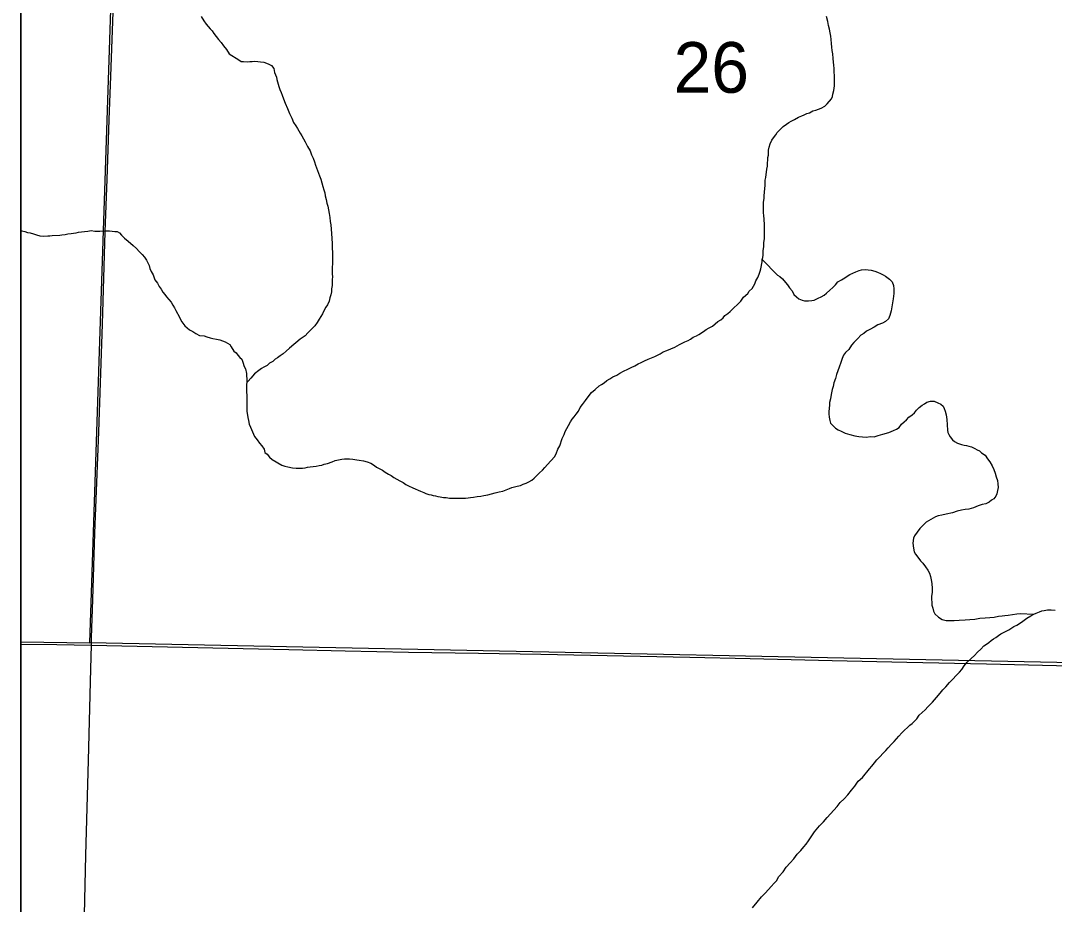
# Model space of a CAD drawing. Extents: x 2.4 to 73.1, y 4.5 to 25.6.
# Drawn here: x 29.4974 to 29.9242, y 22.0706 to 22.4355 of the extents above; entities that cross this region are included whole.
import ezdxf

# ---------------------------------------------------------------- set-up
doc = ezdxf.new("R2010")
doc.units = 0
for name, color, linetype in [('GM_X_County_Road', 7, 'Continuous'), ('GM_X_Interchange_Ramps', 7, 'Continuous'), ('GM_X_Minor_River', 7, 'Continuous'), ('GM_X_Section', 7, 'Continuous'), ('GM_X_Section_Text', 7, 'Continuous'), ('GM_X_Township_Road', 7, 'Continuous'), ('GM_X_US_Shield', 7, 'Continuous'), ('SH_Cut_Line', 7, 'Continuous'), ('SH_Data', 7, 'Continuous')]:
    doc.layers.add(name, color=color, linetype=linetype)

msp = doc.modelspace()

# ---------------------------------------------------------------- linework, layer by layer
at = {"layer": 'GM_X_County_Road'}
for points in [[(29.49738, 22.17807), (29.51234, 22.17781), (29.52657, 22.17755)], [(29.52657, 22.17755), (29.60806, 22.17578), (29.63137, 22.17527), (29.65748, 22.17474), (29.68638, 22.17428), (29.71218, 22.17383), (29.77371, 22.17258), (29.79858, 22.17203), (29.83246, 22.17129), (29.86322, 22.17062), (29.89616, 22.16995), (29.92506, 22.16924), (29.98504, 22.16792), (30.01954, 22.16724), (30.02726, 22.16709)]]:
    msp.add_lwpolyline(points, dxfattribs=at)
at = {"layer": 'GM_X_Interchange_Ramps'}
msp.add_lwpolyline([(29.49738, 24.68879), (29.49738, 21.67933)], dxfattribs=at)
at = {"layer": 'GM_X_Minor_River'}
for points in [[(29.57195, 22.43721), (29.57306, 22.43548), (29.57399, 22.43413), (29.57474, 22.43317), (29.57567, 22.43221), (29.57642, 22.43125), (29.57717, 22.43028), (29.5781, 22.42894), (29.57903, 22.42779), (29.58015, 22.42644), (29.58108, 22.42509), (29.58238, 22.42355), (29.5835, 22.42182), (29.58745, 22.41929), (29.58839, 22.41871), (29.58935, 22.41869), (29.59086, 22.41848), (29.59201, 22.41865), (29.59296, 22.41863), (29.59391, 22.41881), (29.59524, 22.4186), (29.59638, 22.41858), (29.59771, 22.41837), (29.59884, 22.41797), (29.59979, 22.41757), (29.60092, 22.41699), (29.60185, 22.41583)], [(29.79336, 22.31836), (29.79472, 22.31967), (29.79588, 22.32136), (29.79762, 22.32286), (29.7982, 22.3238), (29.79936, 22.32492), (29.79995, 22.32586), (29.80053, 22.3268), (29.80093, 22.32812), (29.80172, 22.32944), (29.80231, 22.33076), (29.80271, 22.33209), (29.80291, 22.33303), (29.80353, 22.33587), (29.80354, 22.33682), (29.80375, 22.33777), (29.80395, 22.33872), (29.80397, 22.33967), (29.80398, 22.34062), (29.8042, 22.34213), (29.80422, 22.34384), (29.80444, 22.34536), (29.80445, 22.34631), (29.80448, 22.34783), (29.80449, 22.34897), (29.80451, 22.35011), (29.80453, 22.35125), (29.80438, 22.35353), (29.80421, 22.35505), (29.80404, 22.3562), (29.80406, 22.35753), (29.80407, 22.35848), (29.80409, 22.35961), (29.8041, 22.36056), (29.80432, 22.36208), (29.80434, 22.36322), (29.80457, 22.36626), (29.80478, 22.36739), (29.8048, 22.36872), (29.80482, 22.36967), (29.80503, 22.37081), (29.80523, 22.37195), (29.80525, 22.3729), (29.80546, 22.37422), (29.80567, 22.37536), (29.80569, 22.37669), (29.8059, 22.37802), (29.80591, 22.37897), (29.80612, 22.37991), (29.80614, 22.38105), (29.80615, 22.382), (29.80636, 22.38333), (29.80676, 22.38465), (29.80755, 22.38616), (29.80814, 22.3871), (29.80911, 22.38842), (29.80969, 22.38936), (29.81066, 22.39029), (29.8122, 22.39179), (29.81355, 22.39272), (29.81451, 22.39346), (29.81547, 22.39402), (29.81681, 22.39475), (29.81854, 22.39568), (29.81988, 22.39623), (29.82083, 22.39659), (29.82198, 22.39714), (29.82313, 22.3975), (29.82448, 22.39824), (29.82562, 22.3986), (29.82677, 22.39897), (29.82791, 22.39933), (29.82945, 22.40025), (29.83042, 22.40119), (29.83216, 22.40325), (29.83256, 22.4042), (29.83276, 22.40514), (29.83316, 22.40666), (29.83339, 22.40855), (29.83341, 22.41007), (29.83343, 22.41159), (29.83345, 22.41292), (29.83328, 22.41425), (29.83331, 22.41577), (29.83314, 22.41711), (29.83297, 22.41844), (29.8328, 22.41996), (29.83264, 22.42186), (29.83247, 22.4232), (29.8323, 22.42453), (29.83214, 22.42605), (29.83197, 22.42776), (29.83181, 22.4291), (29.83164, 22.43043), (29.83128, 22.43196), (29.83092, 22.43348), (29.83057, 22.4352), (29.83003, 22.4373)], [(29.60185, 22.41583), (29.60221, 22.41412), (29.60257, 22.41316), (29.60294, 22.4122), (29.60311, 22.41125), (29.60348, 22.4103), (29.60365, 22.40934), (29.60402, 22.40839), (29.60438, 22.40705), (29.60493, 22.4059), (29.60529, 22.40476), (29.60584, 22.40323), (29.60657, 22.40151), (29.60749, 22.39921), (29.60841, 22.39711), (29.60933, 22.39519), (29.61006, 22.39347), (29.61099, 22.39213), (29.61173, 22.39097), (29.61229, 22.39002), (29.61284, 22.38906), (29.6134, 22.38791), (29.61414, 22.38676), (29.61488, 22.38541), (29.6158, 22.3835), (29.61691, 22.38177), (29.61746, 22.38005), (29.6182, 22.37871), (29.61875, 22.37718), (29.6191, 22.37585), (29.62038, 22.3726), (29.62075, 22.37145), (29.6213, 22.37011), (29.62165, 22.36859), (29.6222, 22.36706), (29.62256, 22.36572), (29.62292, 22.36439), (29.62309, 22.36324), (29.62345, 22.36172), (29.6238, 22.36019), (29.62416, 22.35886), (29.62452, 22.35733), (29.62469, 22.35581), (29.62504, 22.35428), (29.62521, 22.35257), (29.62537, 22.35124), (29.62553, 22.34934), (29.6257, 22.34762), (29.62586, 22.34553), (29.62601, 22.34344), (29.62598, 22.34154), (29.62615, 22.33982), (29.62612, 22.33812), (29.6261, 22.3366), (29.62607, 22.33507), (29.62605, 22.33375), (29.62603, 22.33223), (29.62601, 22.3309), (29.62618, 22.32975), (29.62597, 22.32862), (29.62595, 22.32729), (29.62593, 22.32615), (29.62572, 22.32482), (29.6257, 22.32349), (29.62549, 22.32235), (29.62509, 22.32103), (29.62469, 22.31971), (29.6241, 22.3182), (29.62332, 22.31726), (29.62273, 22.31594), (29.62194, 22.31443), (29.62136, 22.3133), (29.62058, 22.31217), (29.6198, 22.31085), (29.61883, 22.30954), (29.61767, 22.30842), (29.6167, 22.30748), (29.61593, 22.30655), (29.61477, 22.30542), (29.61284, 22.30393), (29.60841, 22.3002), (29.60706, 22.29909), (29.60571, 22.29797), (29.60456, 22.29704), (29.6034, 22.29629), (29.60244, 22.29574), (29.60148, 22.2948), (29.60014, 22.29407), (29.59917, 22.29313), (29.59783, 22.29239), (29.59687, 22.29184), (29.59571, 22.2911), (29.59398, 22.2896), (29.59243, 22.28792), (29.59127, 22.28661), (29.59088, 22.28623), (29.59089, 22.28642)], [(29.49738, 22.34879), (29.49791, 22.3487), (29.49905, 22.34849), (29.50018, 22.34809), (29.50132, 22.34788), (29.50265, 22.34748), (29.50397, 22.34708), (29.5053, 22.34668), (29.50681, 22.34647), (29.50853, 22.34663), (29.50948, 22.34661), (29.51043, 22.34679), (29.51348, 22.34693), (29.51443, 22.3471), (29.51577, 22.34727), (29.51691, 22.34745), (29.51824, 22.34761), (29.5192, 22.34779), (29.52034, 22.34796), (29.52129, 22.34814), (29.52244, 22.34831), (29.52377, 22.34848), (29.52511, 22.34865), (29.52644, 22.34881), (29.52796, 22.3486), (29.53005, 22.34857), (29.53196, 22.34873), (29.53405, 22.34869), (29.53632, 22.34847), (29.53728, 22.34845), (29.53822, 22.34787), (29.53896, 22.34691), (29.54028, 22.34575), (29.54178, 22.34439), (29.54384, 22.34265), (29.54515, 22.34149), (29.54627, 22.34014), (29.54759, 22.33898), (29.54852, 22.33782), (29.54926, 22.33667), (29.54982, 22.33552), (29.55037, 22.33438), (29.55073, 22.33323), (29.55128, 22.33189), (29.55202, 22.33055), (29.55275, 22.32845), (29.55387, 22.3271), (29.55461, 22.32576), (29.55535, 22.32461), (29.55609, 22.32345), (29.55684, 22.32249), (29.55758, 22.32153), (29.55852, 22.32038), (29.55945, 22.31922), (29.56019, 22.31807), (29.56093, 22.31692), (29.56149, 22.31577), (29.56297, 22.31308), (29.56333, 22.31213), (29.56389, 22.31117), (29.56519, 22.30944), (29.56613, 22.30866), (29.56707, 22.30789), (29.56839, 22.30711), (29.56971, 22.30633)], [(29.80354, 22.33682), (29.80991, 22.33045), (29.81085, 22.32987), (29.81198, 22.3289), (29.81309, 22.32736), (29.81403, 22.3264), (29.81477, 22.32524), (29.81589, 22.3239), (29.81663, 22.32236), (29.81776, 22.3214), (29.81869, 22.32062), (29.82002, 22.32003), (29.82096, 22.31983), (29.82268, 22.3198), (29.82401, 22.31997), (29.82496, 22.32014), (29.82669, 22.32088), (29.82784, 22.32143), (29.82918, 22.32217), (29.83014, 22.32291), (29.83149, 22.32422), (29.83265, 22.32534), (29.83381, 22.32646), (29.83478, 22.32759), (29.83631, 22.32851), (29.83766, 22.32925), (29.83862, 22.33), (29.83977, 22.33074), (29.84092, 22.33129), (29.84226, 22.33184), (29.8436, 22.33239), (29.84456, 22.33256), (29.84608, 22.33273), (29.84855, 22.3325), (29.85006, 22.33209), (29.8512, 22.3317), (29.85233, 22.33111), (29.85346, 22.33052), (29.85441, 22.32994), (29.8561, 22.32877), (29.85722, 22.32761), (29.85777, 22.32608), (29.85794, 22.32475), (29.85791, 22.32285), (29.85768, 22.32057), (29.85726, 22.31811), (29.85684, 22.31565), (29.85624, 22.31376), (29.85565, 22.31244), (29.85449, 22.31131), (29.85315, 22.31057), (29.85124, 22.30985), (29.8497, 22.30892), (29.84798, 22.308), (29.84663, 22.30726), (29.84548, 22.30633), (29.84432, 22.30559), (29.84297, 22.30428), (29.84142, 22.30259), (29.84046, 22.30147), (29.83929, 22.29977), (29.83794, 22.29847), (29.83716, 22.29734), (29.83657, 22.29602), (29.83597, 22.29432), (29.83537, 22.29243), (29.83477, 22.29092), (29.83418, 22.28941), (29.83377, 22.2877), (29.83318, 22.286), (29.83277, 22.28449), (29.83237, 22.28316), (29.83196, 22.28108), (29.83174, 22.27937), (29.83134, 22.27786), (29.83132, 22.27672), (29.83109, 22.27406), (29.83107, 22.27311), (29.83124, 22.27178), (29.83141, 22.27045), (29.83177, 22.2693), (29.83383, 22.26718), (29.83496, 22.26659), (29.8361, 22.266), (29.8378, 22.26522), (29.83969, 22.26462), (29.84177, 22.26401), (29.84348, 22.2638), (29.845, 22.26358), (29.84652, 22.26356), (29.84823, 22.26372), (29.84975, 22.2637), (29.85147, 22.26424), (29.85338, 22.26478), (29.85587, 22.2655), (29.85778, 22.26623), (29.85893, 22.26678), (29.86008, 22.26752), (29.86105, 22.26884), (29.86221, 22.26977), (29.86318, 22.2707)], [(29.66964, 22.239), (29.67059, 22.2388), (29.67192, 22.23859), (29.67306, 22.23857), (29.67439, 22.23836), (29.67572, 22.23834), (29.67705, 22.23831), (29.67838, 22.23829), (29.67971, 22.23827), (29.68104, 22.23825), (29.68218, 22.23842), (29.68314, 22.2386), (29.68428, 22.23877), (29.68581, 22.23894), (29.68733, 22.2391), (29.68867, 22.23946), (29.69019, 22.23963), (29.69172, 22.24017), (29.69325, 22.24053), (29.69496, 22.24088), (29.69649, 22.24124), (29.69783, 22.24179), (29.69917, 22.24233), (29.70013, 22.2427), (29.70128, 22.24306), (29.70242, 22.24323), (29.70376, 22.24359), (29.70491, 22.24414), (29.70605, 22.2445), (29.7072, 22.24506), (29.70836, 22.2458), (29.70932, 22.24654), (29.71067, 22.24785), (29.71164, 22.24879), (29.71279, 22.24991), (29.71376, 22.25103), (29.71492, 22.25215), (29.71782, 22.25534), (29.71842, 22.25666), (29.71921, 22.25855), (29.71999, 22.25986), (29.72099, 22.26289), (29.72177, 22.26459), (29.72217, 22.26591), (29.72354, 22.26836), (29.72433, 22.26987), (29.72511, 22.27099), (29.72588, 22.27193), (29.72666, 22.27306), (29.72763, 22.27418), (29.72841, 22.27569), (29.72938, 22.27701), (29.73055, 22.2787), (29.73172, 22.2802), (29.73307, 22.28189), (29.73462, 22.28319), (29.73616, 22.28469), (29.73712, 22.28524), (29.73827, 22.28599), (29.73943, 22.28692), (29.74058, 22.28766), (29.74192, 22.2884), (29.74346, 22.28913), (29.7448, 22.28987), (29.74634, 22.2908), (29.74806, 22.29153), (29.7494, 22.29227), (29.75094, 22.29301), (29.75228, 22.29374), (29.75362, 22.29429), (29.75496, 22.29503), (29.75649, 22.29577), (29.75783, 22.29632), (29.75917, 22.29686), (29.76032, 22.29742), (29.76147, 22.29797), (29.76263, 22.29871), (29.76416, 22.29926), (29.76741, 22.30072), (29.76837, 22.30128), (29.76933, 22.30183), (29.77048, 22.30239), (29.77163, 22.30294), (29.77297, 22.30349), (29.77393, 22.30404), (29.77508, 22.30478), (29.77642, 22.30533), (29.77738, 22.30589), (29.7793, 22.30719), (29.78046, 22.30793), (29.78161, 22.30867), (29.78295, 22.30941), (29.78411, 22.31034), (29.78527, 22.31127), (29.78642, 22.31201), (29.78738, 22.31276), (29.78816, 22.3137), (29.78931, 22.31463), (29.79027, 22.31537), (29.79182, 22.31687), (29.79336, 22.31836)], [(29.56971, 22.30633), (29.57122, 22.30554), (29.57312, 22.30532), (29.57425, 22.30493), (29.57558, 22.30452), (29.57671, 22.30432), (29.57823, 22.30391), (29.57956, 22.3037), (29.58069, 22.3033), (29.58183, 22.30291), (29.58277, 22.30232), (29.58371, 22.30174), (29.58426, 22.30078), (29.58538, 22.29905), (29.58632, 22.29827), (29.58706, 22.29731), (29.58781, 22.29635), (29.58875, 22.29577), (29.58911, 22.29443), (29.58965, 22.29271), (29.59021, 22.29175), (29.59056, 22.28985), (29.59055, 22.2889), (29.59071, 22.28756), (29.59069, 22.28624), (29.59068, 22.28529), (29.59066, 22.28415), (29.59064, 22.283), (29.59063, 22.28206), (29.5908, 22.28091), (29.59078, 22.27958), (29.59075, 22.27787), (29.59074, 22.27692), (29.59072, 22.27578), (29.59069, 22.27407), (29.59105, 22.27255), (29.59123, 22.2716), (29.5914, 22.27045), (29.59175, 22.26893), (29.5923, 22.26759), (29.59303, 22.26568), (29.59396, 22.26376), (29.59508, 22.26241), (29.596, 22.26107), (29.59694, 22.25991), (29.59787, 22.25857), (29.59823, 22.25723), (29.59917, 22.25646), (29.6001, 22.2553), (29.60123, 22.25434), (29.60518, 22.25199), (29.60651, 22.25159), (29.60764, 22.2512), (29.60954, 22.25078), (29.61106, 22.25076), (29.61239, 22.25074), (29.61372, 22.25072), (29.61486, 22.25089), (29.61582, 22.25107), (29.61696, 22.25124), (29.61811, 22.25141), (29.61944, 22.25158), (29.62058, 22.25175), (29.62173, 22.25192), (29.62268, 22.25229), (29.62402, 22.25265), (29.62593, 22.25338), (29.62727, 22.25392), (29.62861, 22.25409), (29.62994, 22.25445), (29.63109, 22.25462), (29.63223, 22.25461), (29.63318, 22.25459), (29.63451, 22.25438), (29.63622, 22.25416), (29.63716, 22.25396), (29.63887, 22.25374), (29.64039, 22.25334), (29.6419, 22.25274), (29.64341, 22.25177), (29.64435, 22.25118), (29.64567, 22.2504), (29.6468, 22.24981), (29.64793, 22.24904), (29.64925, 22.24825), (29.65038, 22.24767), (29.65151, 22.24689), (29.65264, 22.24611), (29.65396, 22.24552), (29.65528, 22.24474), (29.65641, 22.24396), (29.65754, 22.24337), (29.65924, 22.24259), (29.66245, 22.24121), (29.66377, 22.24061), (29.66472, 22.24022), (29.66585, 22.23982), (29.6668, 22.23962), (29.66775, 22.23941), (29.66869, 22.23921), (29.66964, 22.239)], [(29.86318, 22.2707), (29.86414, 22.27183), (29.86549, 22.27276), (29.86645, 22.2735), (29.86723, 22.27463), (29.86839, 22.27575), (29.86955, 22.27668), (29.8705, 22.27724), (29.87147, 22.27798), (29.873, 22.27834), (29.87452, 22.27832), (29.87603, 22.27772), (29.87735, 22.27713), (29.87829, 22.27636), (29.87866, 22.2754), (29.87902, 22.27425), (29.87956, 22.27273), (29.87972, 22.27082), (29.88004, 22.26645), (29.88021, 22.26549), (29.88058, 22.26454), (29.88113, 22.26358), (29.88207, 22.26243), (29.883, 22.26165), (29.88414, 22.26106), (29.88584, 22.26047), (29.88698, 22.26026), (29.88792, 22.26005), (29.88887, 22.25985), (29.89001, 22.25945), (29.89133, 22.25886), (29.89227, 22.25827), (29.89321, 22.25788), (29.89415, 22.2571), (29.89566, 22.25613), (29.89659, 22.25459), (29.89752, 22.25325), (29.89844, 22.25171), (29.89918, 22.25018), (29.89973, 22.24865), (29.90008, 22.24713), (29.90063, 22.2456), (29.9008, 22.24427), (29.90096, 22.24274), (29.90075, 22.24142), (29.90035, 22.24009), (29.89996, 22.23915), (29.89918, 22.23802), (29.89822, 22.23747), (29.89726, 22.23672), (29.89591, 22.23598), (29.89439, 22.23563), (29.89267, 22.23509), (29.89075, 22.23436), (29.88884, 22.23382), (29.88732, 22.23365), (29.88579, 22.2333), (29.88408, 22.23294), (29.88216, 22.23221), (29.87949, 22.23168), (29.87777, 22.23133), (29.87625, 22.23098), (29.8751, 22.23061), (29.87414, 22.23006), (29.87126, 22.2284), (29.8701, 22.22727), (29.86856, 22.22578), (29.86758, 22.22427), (29.86642, 22.22277), (29.86602, 22.22183), (29.8658, 22.21974), (29.86596, 22.21765), (29.86631, 22.21612), (29.86687, 22.21516), (29.86817, 22.21343), (29.86892, 22.21247), (29.86986, 22.21151), (29.87097, 22.20997), (29.8719, 22.20863), (29.87264, 22.20728), (29.873, 22.20595), (29.87336, 22.20461), (29.87353, 22.20309), (29.87369, 22.201), (29.87366, 22.19929), (29.87344, 22.19777), (29.87342, 22.19644), (29.8736, 22.1953), (29.87358, 22.19416), (29.87394, 22.19282), (29.8743, 22.19168), (29.87485, 22.19053), (29.87635, 22.18917), (29.87786, 22.1882), (29.87956, 22.18779), (29.88108, 22.18777), (29.8828, 22.18774), (29.88489, 22.1879), (29.88737, 22.18805), (29.88927, 22.18821), (29.89136, 22.18836)], [(29.89136, 22.18836), (29.89346, 22.18871), (29.89556, 22.18887), (29.89746, 22.18903), (29.89937, 22.18919), (29.90108, 22.18954), (29.90261, 22.18971), (29.90375, 22.18988), (29.90508, 22.19005), (29.90871, 22.19056), (29.91004, 22.19073), (29.91574, 22.19045)], [(29.89904, 22.18026), (29.9, 22.18082), (29.90115, 22.18156), (29.90211, 22.1823), (29.90537, 22.18396), (29.90748, 22.18526), (29.90863, 22.18581), (29.90978, 22.18655), (29.91113, 22.18748), (29.91286, 22.18878), (29.9144, 22.18971), (29.91574, 22.19045), (29.9167, 22.19081), (29.91804, 22.19136), (29.91899, 22.19173), (29.91995, 22.1919), (29.92128, 22.19226), (29.92281, 22.19224), (29.92451, 22.19202)], [(29.91066, 22.19072), (29.91061, 22.19072)], [(29.79954, 22.06917), (29.80148, 22.07142), (29.80322, 22.07367), (29.80477, 22.07516), (29.80612, 22.07666), (29.80728, 22.07797), (29.80845, 22.07929), (29.80941, 22.08022), (29.81039, 22.08211), (29.81213, 22.08398), (29.8135, 22.08586), (29.81505, 22.08773), (29.81659, 22.08942), (29.81795, 22.0913), (29.8195, 22.09279), (29.82066, 22.09429), (29.82163, 22.09542), (29.8226, 22.09673), (29.82377, 22.09842), (29.82514, 22.10049), (29.82726, 22.10293), (29.82881, 22.10461), (29.83036, 22.10649), (29.83172, 22.10799), (29.83307, 22.10949), (29.83443, 22.11099), (29.83579, 22.11267), (29.83733, 22.11417), (29.83888, 22.11585), (29.84043, 22.11773), (29.84179, 22.11942), (29.84315, 22.12149), (29.84489, 22.12298), (29.84779, 22.12654), (29.84876, 22.12767), (29.84992, 22.12898), (29.8509, 22.13029), (29.85225, 22.1316), (29.85341, 22.13291), (29.85457, 22.13404), (29.85554, 22.13516), (29.85689, 22.13666), (29.85805, 22.13778), (29.85902, 22.13891), (29.85999, 22.14003), (29.86115, 22.14134), (29.86231, 22.14246), (29.86347, 22.14359), (29.86443, 22.14452), (29.86539, 22.14527), (29.86636, 22.1462), (29.86733, 22.14713), (29.8683, 22.14864), (29.86965, 22.14976), (29.87081, 22.15088), (29.87197, 22.15219), (29.87293, 22.15313), (29.8739, 22.15406), (29.87468, 22.155), (29.87545, 22.15594), (29.877, 22.15781), (29.87816, 22.15912), (29.87933, 22.16044), (29.88087, 22.16212), (29.88223, 22.16362), (29.88358, 22.16512), (29.88494, 22.16643), (29.8859, 22.16755), (29.88688, 22.16906), (29.88823, 22.17055), (29.88978, 22.17205), (29.89113, 22.17336), (29.89248, 22.17467), (29.89383, 22.17598), (29.89499, 22.17729), (29.89615, 22.17803), (29.89711, 22.17877), (29.89807, 22.17952), (29.89904, 22.18026)]]:
    msp.add_lwpolyline(points, dxfattribs=at)
at = {"layer": 'GM_X_Section'}
msp.add_lwpolyline([(30.03874, 22.66769), (30.02677, 22.1684), (29.52592, 22.17851), (29.54241, 22.67676)], close=True, dxfattribs=at)
at = {"layer": 'GM_X_Township_Road'}
for points in [[(29.52657, 22.17755), (29.52665, 22.18061), (29.52711, 22.19645), (29.52806, 22.22379), (29.5296, 22.26572), (29.53111, 22.31013), (29.53223, 22.34834), (29.53305, 22.37008), (29.53392, 22.39462), (29.53461, 22.41263), (29.53579, 22.4468), (29.5365, 22.46574), (29.53724, 22.48904), (29.53768, 22.50208), (29.53862, 22.52942), (29.53977, 22.56016), (29.54064, 22.58159), (29.54174, 22.61389), (29.5425, 22.63626), (29.54333, 22.66235), (29.54351, 22.67632)], [(29.51243, 21.67882), (29.51353, 21.69522), (29.51489, 21.73819), (29.51728, 21.81834), (29.51841, 21.85656), (29.51942, 21.89228), (29.52091, 21.95007), (29.52144, 21.97151), (29.52235, 22.01222), (29.5237, 22.06628), (29.5243, 22.09082), (29.52537, 22.12997), (29.52634, 22.16787), (29.52657, 22.17755)]]:
    msp.add_lwpolyline(points, dxfattribs=at)
at = {"layer": 'GM_X_US_Shield'}
msp.add_lwpolyline([(29.49738, 22.67773), (29.49738, 22.17902), (29.52592, 22.17851), (29.54241, 22.67676)], close=True, dxfattribs=at)
at = {"layer": 'SH_Cut_Line'}
msp.add_lwpolyline([(29.49738, 24.78522), (29.49738, 21.67933)], dxfattribs=at)
at = {"layer": 'SH_Data'}
msp.add_lwpolyline([(29.49738, 24.78522), (36.29738, 24.78522), (36.29738, 17.98522), (29.49738, 17.98522)], close=True, dxfattribs=at)

# ---------------------------------------------------------------- texts
at = {"layer": 'GM_X_Section_Text'}
msp.add_text('26', height=0.020928, rotation=0, dxfattribs=at).set_placement((29.76695, 22.40574))

doc.saveas('drawing.dxf')
